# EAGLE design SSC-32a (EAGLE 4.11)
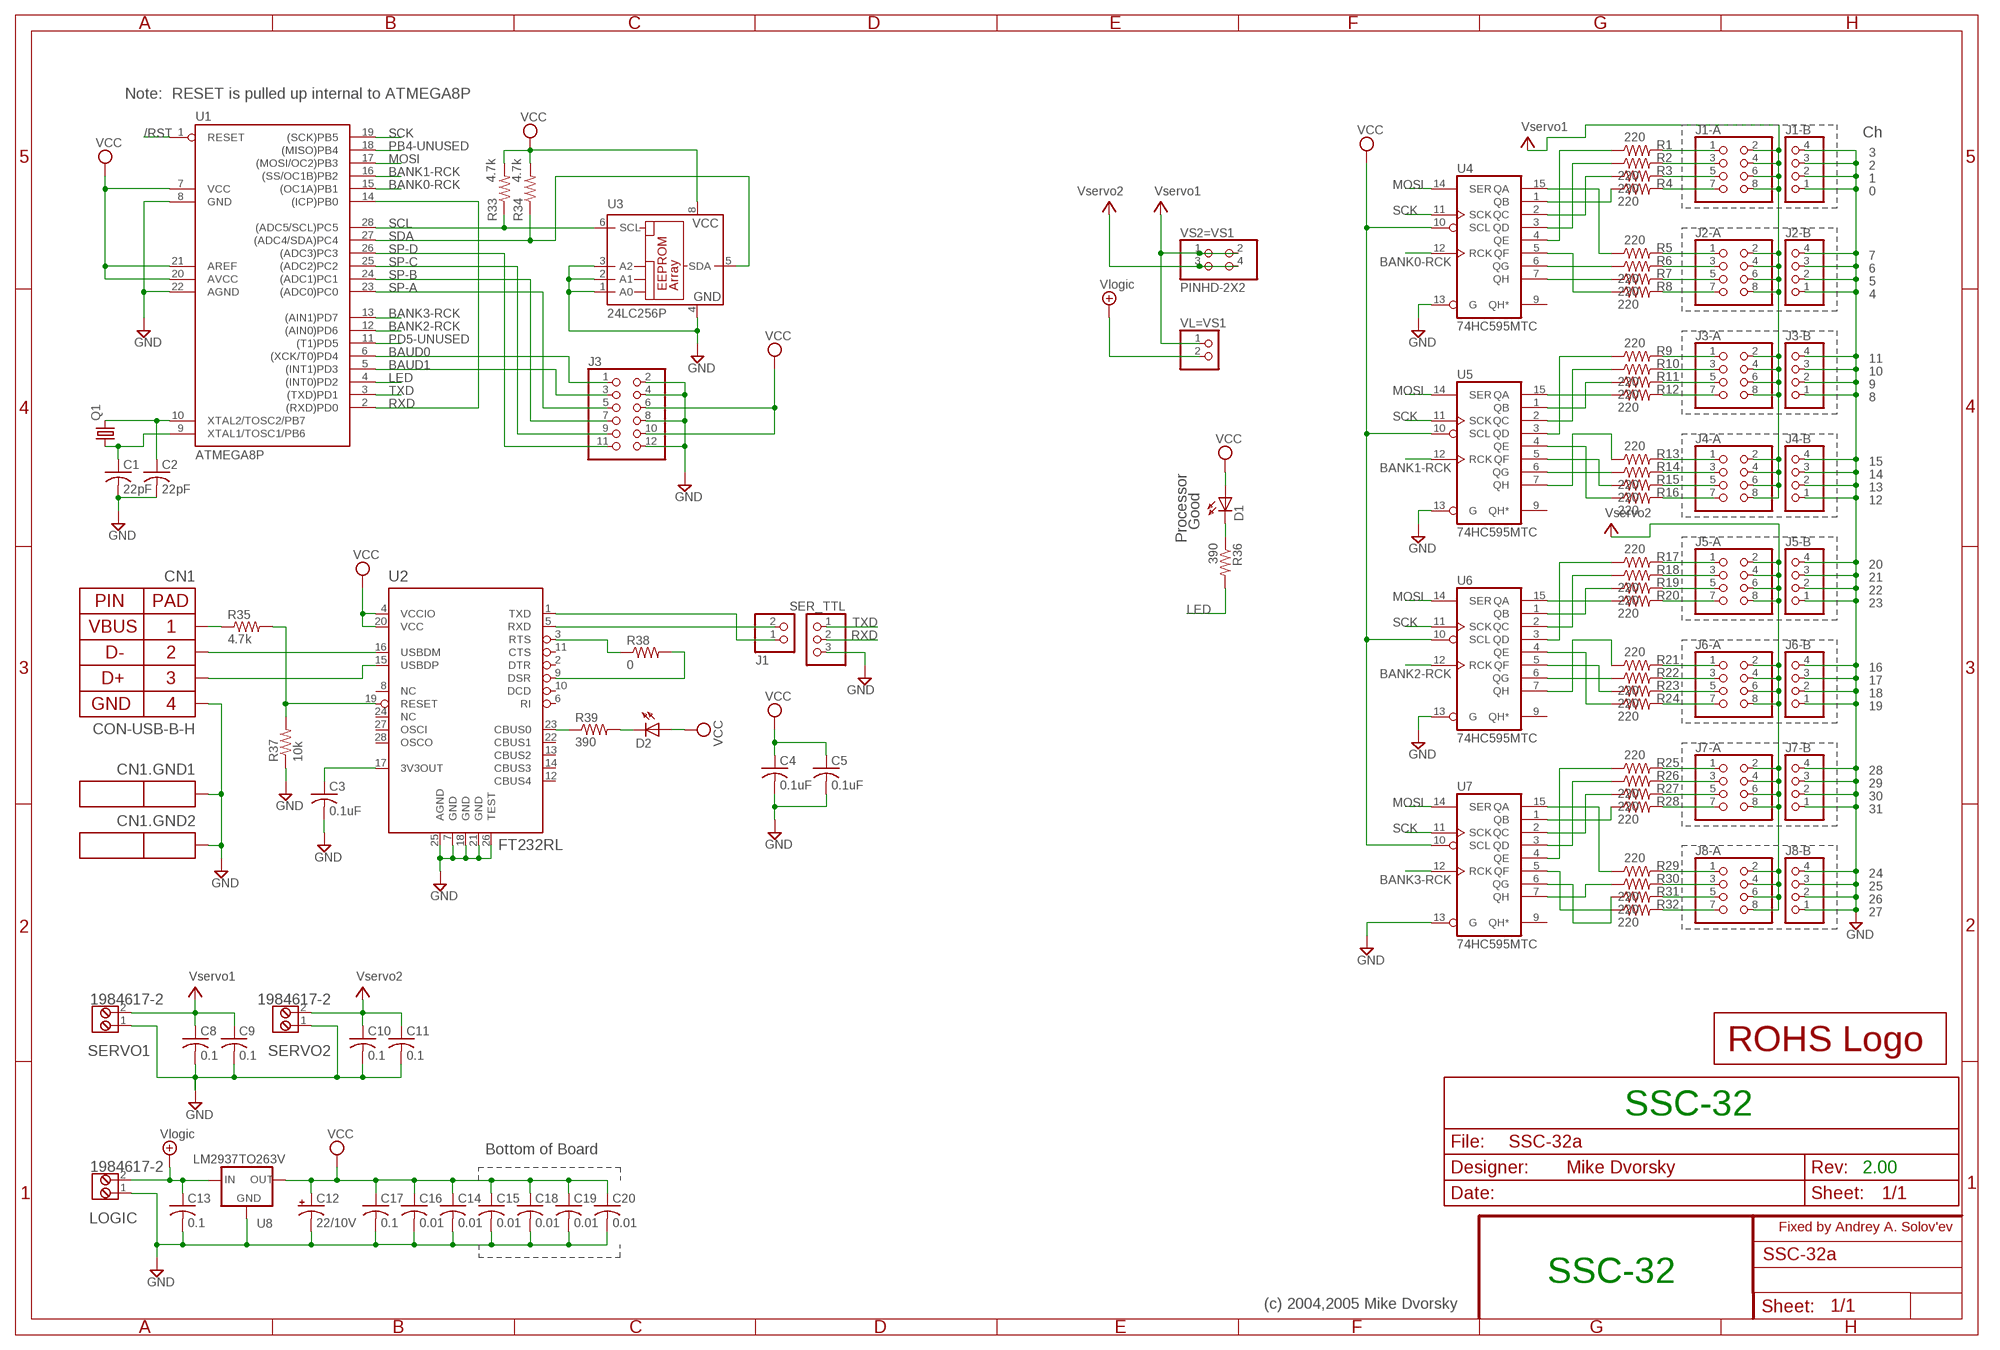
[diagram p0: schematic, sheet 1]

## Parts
C1  22pF  C-USC0603K  [C0603K]
C2  22pF  C-USC0603K  [C0603K]
C3  0.1uF  C-USC0603K  [C0603K]
C4  0.1uF  C-USC0603K  [C0603K]
C5  0.1uF  C-USC0603K  [C0603K]
C8  0.1  C-USC0805K  [C0805K]
C9  0.1  C-USC0805K  [C0805K]
C10  0.1  C-USC0805K  [C0805K]
C11  0.1  C-USC0805K  [C0805K]
C12  22/10V  CPOL-USC/6032-28R  [C/6032-28R]
C13  0.1  C-USC0805K  [C0805K]
C14  0.01  C-USC0603K  [C0603K]
C15  0.01  C-USC0805K  [C0805K]
C16  0.01  C-USC0603K  [C0603K]
C17  0.1  C-USC0805K  [C0805K]
C18  0.01  C-USC0805K  [C0805K]
C19  0.01  C-USC0805K  [C0805K]
C20  0.01  C-USC0805K  [C0805K]
CN1  CON-USB-B-H  [USB-B-H]
D1  LED  [LED-1206]
D2  LED  [LED-1206]
J1  PINHD-1X2SM  [1X02SMALL]
J1-A  PINHD-2X4  [2X04]
J1-B  PINHD-1X4SM"  [1X04SMALL]
J2-A  PINHD-2X4  [2X04]
J2-B  PINHD-1X4SM"  [1X04SMALL]
J3  PINHD-2X6  [2X06]
J3-A  PINHD-2X4  [2X04]
J3-B  PINHD-1X4SM"  [1X04SMALL]
J4-A  PINHD-2X4  [2X04]
J4-B  PINHD-1X4SM"  [1X04SMALL]
J5-A  PINHD-2X4  [2X04]
J5-B  PINHD-1X4SM"  [1X04SMALL]
J6-A  PINHD-2X4  [2X04]
J6-B  PINHD-1X4SM"  [1X04SMALL]
J7-A  PINHD-2X4  [2X04]
J7-B  PINHD-1X4SM"  [1X04SMALL]
J8-A  PINHD-2X4  [2X04]
J8-B  PINHD-1X4SM"  [1X04SMALL]
LOGIC  1984617-2  SCREW_CLAMP2-1984617-2  [1984617-2]
LOGO1  ROHS_LOGO-2_150MIL_TOP  [ROHS_LOGO2_150MIL_TOP]
Q1  CRYTALHC49U-V  [HC49U-V]
R1  220  R-US_R0603  [R0603]
R2  220  R-US_R0603  [R0603]
R3  220  R-US_R0603  [R0603]
R4  220  R-US_R0603  [R0603]
R5  220  R-US_R0603  [R0603]
R6  220  R-US_R0603  [R0603]
R7  220  R-US_R0603  [R0603]
R8  220  R-US_R0603  [R0603]
R9  220  R-US_R0603  [R0603]
R10  220  R-US_R0603  [R0603]
R11  220  R-US_R0603  [R0603]
R12  220  R-US_R0603  [R0603]
R13  220  R-US_R0603  [R0603]
R14  220  R-US_R0603  [R0603]
R15  220  R-US_R0603  [R0603]
R16  220  R-US_R0603  [R0603]
R17  220  R-US_R0603  [R0603]
R18  220  R-US_R0603  [R0603]
R19  220  R-US_R0603  [R0603]
R20  220  R-US_R0603  [R0603]
R21  220  R-US_R0603  [R0603]
R22  220  R-US_R0603  [R0603]
R23  220  R-US_R0603  [R0603]
R24  220  R-US_R0603  [R0603]
R25  220  R-US_R0603  [R0603]
R26  220  R-US_R0603  [R0603]
R27  220  R-US_R0603  [R0603]
R28  220  R-US_R0603  [R0603]
R29  220  R-US_R0603  [R0603]
R30  220  R-US_R0603  [R0603]
R31  220  R-US_R0603  [R0603]
R32  220  R-US_R0603  [R0603]
R33  4.7k  R-US_R0603  [R0603]
R34  4.7k  R-US_R0603  [R0603]
R35  4.7k  R-US_R0603  [R0603]
R36  390  R-US_R0603  [R0603]
R37  10k  R-US_R0603  [R0603]
R38  0  R-US_R0603  [R0603]
R39  390  R-US_R0603  [R0603]
SER_TTL  PINHD-1X3SM  [1X03SMALL]
SERVO1  1984617-2  SCREW_CLAMP2-1984617-2  [1984617-2]
SERVO2  1984617-2  SCREW_CLAMP2-1984617-2  [1984617-2]
U1  ATMEGA8P  [DIL28-3]
U2  FT232RL  [SSOP28DB]
U3  24LC256P  24-LC32P  [DIL8]
U4  74HC595MTC  74595MTC  [TSSOP16]
U5  74HC595MTC  74595MTC  [TSSOP16]
U6  74HC595MTC  74595MTC  [TSSOP16]
U7  74HC595MTC  74595MTC  [TSSOP16]
U8  LM2937TO263V  [TO263V]
VL=VS1  PINHD-1X2SM  [1X02SMALL]
VS2=VS1  PINHD-2X2  [2X02]

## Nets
/RST: U1.1(RESET)
BANK0-RCK: U1.15((OC1A)PB1) U4.12(RCK)
BANK1-RCK: U1.16((SS/OC1B)PB2) U5.12(RCK)
BANK2-RCK: U1.12((AIN0)PD6) U6.12(RCK)
BANK3-RCK: U1.13((AIN1)PD7) U7.12(RCK)
BAUD0: J3.1 U1.6((XCK/T0)PD4)
BAUD1: J3.3 U1.5((INT1)PD3)
GND: C1.2 C2.2 C3.2 C4.2 C5.2 C8.2 C9.2 C10.2 C11.2 C12.- C13.2 C14.2 C15.2 C16.2 C17.2 C18.2 C19.2 C20.2 CN1.GND CN1.GND@1 CN1.GND@2 J1-B.1 J1-B.2 J1-B.3 J1-B.4 J2-B.1 J2-B.2 J2-B.3 J2-B.4 J3-B.1 J3-B.2 J3-B.3 J3-B.4 J3.2 J3.4 J3.8 J3.12 J4-B.1 J4-B.2 J4-B.3 J4-B.4 J5-B.1 J5-B.2 J5-B.3 J5-B.4 J6-B.1 J6-B.2 J6-B.3 J6-B.4 J7-B.1 J7-B.2 J7-B.3 J7-B.4 J8-B.1 J8-B.2 J8-B.3 J8-B.4 LOGIC.1 R37.1 SER_TTL.3 SERVO1.1 SERVO2.1 U1.8(GND) U1.22(AGND) U2.7(GND) U2.18(GND) U2.21(GND) U2.25(AGND) U2.26(TEST) U3.1(A0) U3.2(A1) U3.3(A2) U3.4(GND) U4.13(G) U5.13(G) U6.13(G) U7.13(G) U8.2(GND)
LED: R36.2 U1.4((INT0)PD2)
MOSI: U1.17((MOSI/OC2)PB3) U4.14(SER) U5.14(SER) U6.14(SER) U7.14(SER)
N$1: J1-A.1 R1.2
N$2: J1-A.3 R2.2
N$3: J1-A.5 R3.2
N$4: J1-A.7 R4.2
N$5: J2-A.1 R5.2
N$6: J2-A.3 R6.2
N$7: CN1.VBUS R35.1
N$8: J2-A.5 R7.2
N$9: J2-A.7 R8.2
N$10: J3-A.1 R9.2
N$11: J3-A.3 R10.2
N$12: J3-A.5 R11.2
N$13: J3-A.7 R12.2
N$14: J4-A.1 R13.2
N$15: J4-A.3 R14.2
N$16: J4-A.5 R15.2
N$17: J4-A.7 R16.2
N$18: J5-A.1 R17.2
N$19: J5-A.3 R18.2
N$21: J5-A.5 R19.2
N$25: J5-A.7 R20.2
N$26: J6-A.1 R21.2
N$27: J6-A.3 R22.2
N$28: J6-A.5 R23.2
N$29: J6-A.7 R24.2
N$30: J7-A.1 R25.2
N$31: J7-A.3 R26.2
N$32: J7-A.5 R27.2
N$33: J7-A.7 R28.2
N$34: J8-A.1 R29.2
N$35: J8-A.3 R30.2
N$36: J8-A.5 R31.2
N$37: J8-A.7 R32.2
N$38: R5.1 U4.15(QA)
N$39: R6.1 U4.6(QG)
N$40: R7.1 U4.7(QH)
N$41: R8.1 U4.5(QF)
N$42: R1.1 U4.4(QE)
N$43: R2.1 U4.3(QD)
N$44: R3.1 U4.2(QC)
N$45: R4.1 U4.1(QB)
N$46: R12.1 U5.15(QA)
N$47: R9.1 U5.3(QD)
N$48: R17.1 U6.3(QD)
N$49: R24.1 U6.4(QE)
N$50: R16.1 U5.4(QE)
N$51: R15.1 U5.5(QF)
N$52: R10.1 U5.2(QC)
N$53: R11.1 U5.1(QB)
N$54: R14.1 U5.6(QG)
N$55: R13.1 U5.7(QH)
N$56: C2.1 Q1.2 U1.10(XTAL2/TOSC2/PB7)
N$57: C1.1 Q1.1 U1.9(XTAL1/TOSC1/PB6)
N$58: R18.1 U6.2(QC)
N$59: R19.1 U6.1(QB)
N$60: R20.1 U6.15(QA)
N$61: R23.1 U6.5(QF)
N$62: R22.1 U6.6(QG)
N$63: R21.1 U6.7(QH)
N$64: R28.1 U7.1(QB)
N$65: R27.1 U7.2(QC)
N$66: R35.2 R37.2 U2.19(RESET)
N$67: CN1.D- U2.16(USBDM)
N$68: CN1.D+ U2.15(USBDP)
N$69: D1.C R36.1
N$70: C3.1 U2.17(3V3OUT)
N$72: R26.1 U7.3(QD)
N$73: R25.1 U7.4(QE)
N$76: R29.1 U7.15(QA)
N$77: R30.1 U7.7(QH)
N$78: R32.1 U7.5(QF)
N$79: R38.1 U2.3(RTS)
N$80: R31.1 U7.6(QG)
N$81: R39.1 U2.23(CBUS0)
N$82: D2.C R39.2
N$83: R38.2 U2.9(DSR)
N$84: J1.1 U2.1(TXD)
N$85: J1.2 U2.5(RXD)
PB4-UNUSED: U1.18((MISO)PB4)
PD5-UNUSED: U1.11((T1)PD5)
RXD: SER_TTL.2 U1.2((RXD)PD0) U1.14((ICP)PB0)
SCK: U1.19((SCK)PB5) U4.11(SCK) U5.11(SCK) U6.11(SCK) U7.11(SCK)
SCL: R33.1 U1.28((ADC5/SCL)PC5) U3.6(SCL)
SDA: R34.1 U1.27((ADC4/SDA)PC4) U3.5(SDA)
SP-A: J3.5 U1.23((ADC0)PC0)
SP-B: J3.7 U1.24((ADC1)PC1)
SP-C: J3.9 U1.25((ADC2)PC2)
SP-D: J3.11 U1.26((ADC3)PC3)
TXD: SER_TTL.1 U1.3((TXD)PD1)
VCC: C4.1 C5.1 C12.+ C14.1 C15.1 C16.1 C17.1 C18.1 C19.1 C20.1 D1.A D2.A J3.6 J3.10 R33.2 R34.2 U1.7(VCC) U1.20(AVCC) U1.21(AREF) U2.4(VCCIO) U2.20(VCC) U3.8(VCC) U4.10(SCL) U5.10(SCL) U6.10(SCL) U7.10(SCL) U8.3(OUT)
VLOGIC: C13.1 LOGIC.2 U8.1(IN) VL=VS1.2 ; supply symbol labelled Vlogic
VSERVO1: C8.1 C9.1 J1-A.2 J1-A.4 J1-A.6 J1-A.8 J2-A.2 J2-A.4 J2-A.6 J2-A.8 J3-A.2 J3-A.4 J3-A.6 J3-A.8 J4-A.2 J4-A.4 J4-A.6 J4-A.8 SERVO1.2 VL=VS1.1 VS2=VS1.1 VS2=VS1.2 ; supply symbol labelled Vservo1
VSERVO2: C10.1 C11.1 J5-A.2 J5-A.4 J5-A.6 J5-A.8 J6-A.2 J6-A.4 J6-A.6 J6-A.8 J7-A.2 J7-A.4 J7-A.6 J7-A.8 J8-A.2 J8-A.4 J8-A.6 J8-A.8 SERVO2.2 VS2=VS1.3 VS2=VS1.4 ; supply symbol labelled Vservo2
Unconnected: U2.2(DTR) U2.6(RI) U2.8(NC) U2.10(DCD) U2.11(CTS) U2.12(CBUS4) U2.13(CBUS2) U2.14(CBUS3) U2.22(CBUS1) U2.24(NC) U2.27(OSCI) U2.28(OSCO) U4.9(QH*) U5.9(QH*) U6.9(QH*) U7.9(QH*)

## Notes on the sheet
- Note:  RESET is pulled up internal to ATMEGA8P
- Ch
- 3
- 2
- 1
- 0
- 7
- 6
- 5
- 4
- 11
- 10
- 9
- 8
- 15
- 14
- 13
- 12
- Good
- Processor
- 20
- 21
- 22
- 23
- 16
- 17
- 18
- 19
- 28
- 29
- 30
- 31
- 24
- 25
- 26
- 27
- SSC-32
- Bottom of Board
- 2.00
- Fixed by Andrey A. Solov'ev
- SSC-32
- (c) 2004,2005 Mike Dvorsky

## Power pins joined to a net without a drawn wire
GND: U4.8(GND) U5.8(GND) U6.8(GND) U7.8(GND)
VCC: U4.16(VCC) U5.16(VCC) U6.16(VCC) U7.16(VCC)

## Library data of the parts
C1-C5 C8-C11 C13-C20 = rcl:C-US: CAPACITOR, American symbol
C12 = rcl:CPOL-US: POLARIZED CAPACITOR, American symbol
CN1 = ASUSLabs_0:CON-USB: CON USB
D1 D2 = madlib:LED: LED
J1 VL=VS1 = madlib:PINHD-1X2: 2-position pin header, 0.1" centers
J1-A J2-A J3-A J4-A J5-A J6-A J7-A J8-A = madlib:PINHD-2X4
J1-B J2-B J3-B J4-B J5-B J6-B J7-B J8-B = madlib:PINHD-1X4SM
J3 = madlib:PINHD-2X6
LOGIC SERVO1 SERVO2 = ASUSLabs_0:SCREW_CLAMP2
LOGO1 = ASUSLabs_0:ROHS_LOGO
Q1 = crystal:CRYTAL: CRYSTAL
R1-R39 = rcl:R-US_: RESISTOR, American symbol
SER_TTL = madlib:PINHD-1X3: 1x3 pin header
U1 = madlib:ATMEGA8P: 28 pin DIP package, ATMEGA8
U2 = ASUSLabs_0:FT232RL
U3 = microchip:24-*: Serial EEPROM 32 K/64 K, 1.8 V, I2C
U4-U7 = 74xx-us:74*595: 8-bit SHIFT REGISTER, output latch
U8 = madlib:LM2937
VS2=VS1 = madlib:PINHD-2X2

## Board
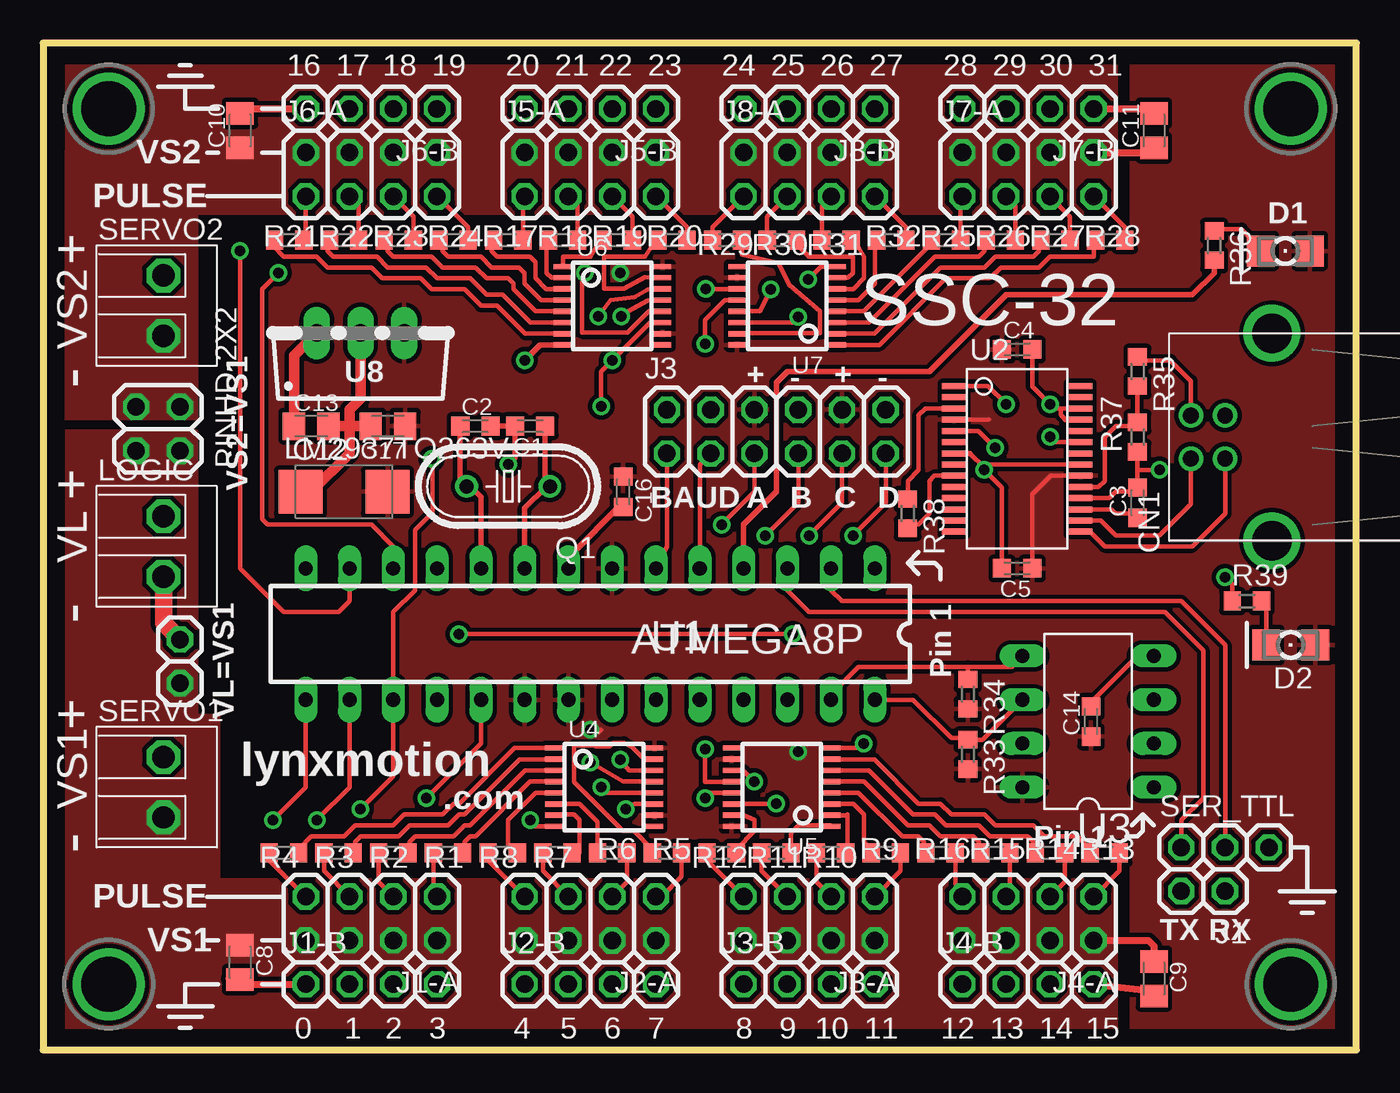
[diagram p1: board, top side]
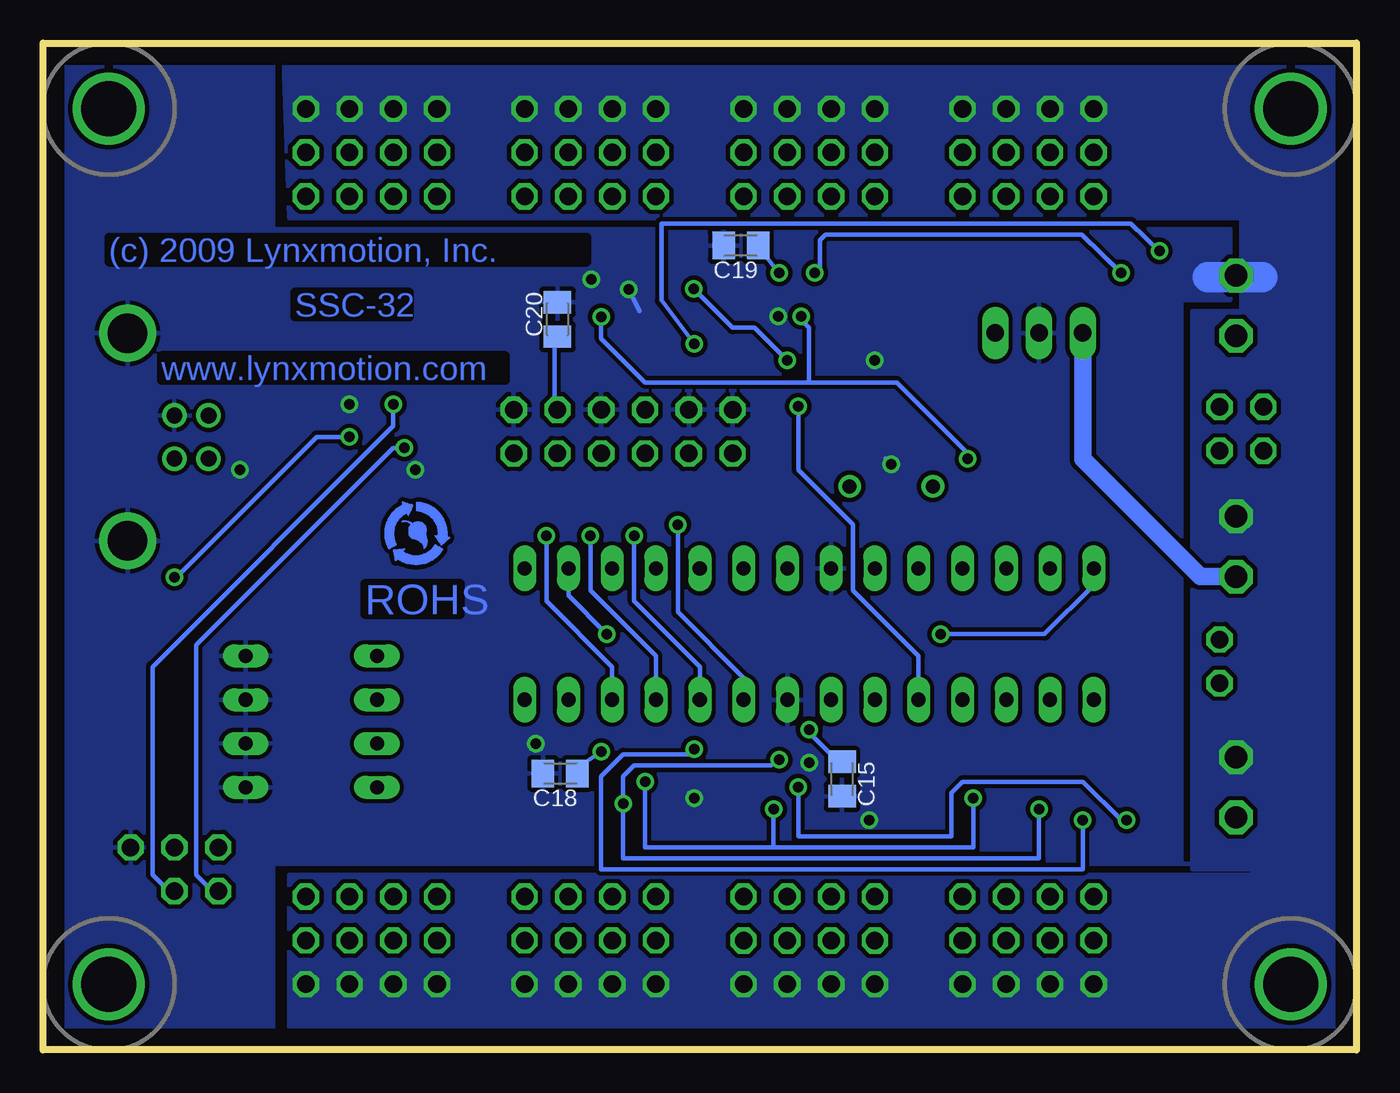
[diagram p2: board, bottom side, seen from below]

Size 76.2 x 58.42 mm. Coordinates in mm from the lower left corner, seen from the top.
Outline: 0,0 76.2,0 76.2,58.42 0,58.42 0,0
Copper layers (1*16): Top 0.035mm / dielectric 1.5mm / Bottom 0.035mm
Design rules "10mils": minimum track width 10mil, minimum drill 24mil, track to track 10mil, track to pad 10mil, pad to pad 10mil, via to via 10mil, smd to smd 10mil, copper to edge 40mil, drill to drill 10mil, minimum pad ring 10mil, minimum via ring 8mil, stop-mask expansion 0mil, vias tented up to drill 0mil, thermal gap 10mil
vRestrict: area 0,0 to 76.2,6.3; area 0,51.4 to 7,58.4; area 69.8,51.4 to 76.2,57.8; area 37.5,45.1 to 44.5,54; area 61,45.7 to 67.9,54.6

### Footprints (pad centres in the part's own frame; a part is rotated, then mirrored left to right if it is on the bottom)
C0603K = smd 1.05 x 1.08: 1 -0.875,0; 2 0.875,0
C0805K = smd 1.3 x 1.6: 1 -1,0; 2 1,0
C/6032-28R = smd 2.55 x 2.5: + 2.525,0; - -2.525,0
USB-B-H = drill 0.914 round: D+ 0,1.25; D- 1.981,1.25; GND 0,-1.25; VBUS 1.981,-1.25 | drill 2.286 round: GND@1 -2.718,-6.02; GND@2 -2.718,6.02
LED-1206 = smd 1.6 x 1.803: A -1.422,0; C 1.422,0
1X02SMALL = drill 1.016 octagon: 1 -1.27,0; 2 1.27,0
2X04 = drill 1.016 octagon: 1 -3.81,-1.27; 2 -3.81,1.27; 3 -1.27,-1.27; 4 -1.27,1.27; 5 1.27,-1.27; 6 1.27,1.27; 7 3.81,-1.27; 8 3.81,1.27
1X04SMALL = drill 1.016 octagon: 1 -3.81,0; 2 -1.27,0; 3 1.27,0; 4 3.81,0
2X06 = drill 1.016 octagon: 1 -6.35,-1.27; 2 -6.35,1.27; 3 -3.81,-1.27; 4 -3.81,1.27; 5 -1.27,-1.27; 6 -1.27,1.27; 7 1.27,-1.27; 8 1.27,1.27; 9 3.81,-1.27; 10 3.81,1.27; 11 6.35,-1.27; 12 6.35,1.27
1984617-2 = drill 1.3 octagon: 1 -1.75,0; 2 1.75,0
HC49U-V = drill 0.813 round: 1 -2.413,0; 2 2.413,0
R0603 = smd 1 x 1.1: 1 -0.85,0; 2 0.85,0
1X03SMALL = drill 1.016 octagon: 1 -2.54,0; 2 0,0; 3 2.54,0
DIL28-3 = drill 0.813 long: 1 -15.24,-3.81; 2 -12.7,-3.81; 3 -10.16,-3.81; 4 -7.62,-3.81; 5 -5.08,-3.81; 6 -2.54,-3.81; 7 0,-3.81; 8 2.54,-3.81; 9 5.08,-3.81; 10 7.62,-3.81; 11 10.16,-3.81; 12 12.7,-3.81; 13 15.24,-3.81; 14 17.78,-3.81; 15 17.78,3.81; 16 15.24,3.81; 17 12.7,3.81; 18 10.16,3.81; 19 7.62,3.81; 20 5.08,3.81; 21 2.54,3.81; 22 0,3.81; 23 -2.54,3.81; 24 -5.08,3.81; 25 -7.62,3.81; 26 -10.16,3.81; 27 -12.7,3.81; 28 -15.24,3.81
SSOP28DB = smd 0.348 x 1.397: 1 -4.225,-3.656; 2 -3.575,-3.656; 3 -2.925,-3.656; 4 -2.275,-3.656; 5 -1.625,-3.656; 6 -0.975,-3.656; 7 -0.325,-3.656; 8 0.325,-3.656; 9 0.975,-3.656; 10 1.625,-3.656; 11 2.275,-3.656; 12 2.925,-3.656; 13 3.575,-3.656; 14 4.225,-3.656; 15 4.225,3.656; 16 3.575,3.656; 17 2.925,3.656; 18 2.275,3.656; 19 1.625,3.656; 20 0.975,3.656; 21 0.325,3.656; 22 -0.325,3.656; 23 -0.975,3.656; 24 -1.625,3.656; 25 -2.275,3.656; 26 -2.925,3.656; 27 -3.575,3.656; 28 -4.225,3.656
DIL8 = drill 0.813 long: 1 -3.81,-3.81; 2 -1.27,-3.81; 3 1.27,-3.81; 4 3.81,-3.81; 5 3.81,3.81; 6 1.27,3.81; 7 -1.27,3.81; 8 -3.81,3.81
TSSOP16 = smd 0.305 x 0.991: 1 -2.275,-2.918; 2 -1.625,-2.918; 3 -0.975,-2.918; 4 -0.325,-2.918; 5 0.325,-2.918; 6 0.975,-2.918; 7 1.625,-2.918; 8 2.275,-2.918; 9 2.275,2.918; 10 1.625,2.918; 11 0.975,2.918; 12 0.325,2.918; 13 -0.325,2.918; 14 -0.975,2.918; 15 -1.625,2.918; 16 -2.275,2.918
TO263V = drill 1.016 long: 1 -2.54,0; 2 0,0; 3 2.54,0
2X02 = drill 1.016 octagon: 1 -1.27,-1.27; 2 -1.27,1.27; 3 1.27,-1.27; 4 1.27,1.27

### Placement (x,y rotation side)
C1  28.26,36.2 180 top
C2  25.08,36.2 0 top
C3  63.5,31.75 90 top
C4  56.52,40.64 0 top
C5  56.52,27.94 180 top
C8  11.43,5.08 270 top
C9  64.45,4.13 270 top
C10  11.43,53.34 90 top
C11  64.45,53.34 90 top
C12  17.46,32.38 0 top
C13  15.56,36.2 0 top
C14  60.8,19.05 90 top
C15  29.84,15.72 270 bottom
C16  33.66,32.38 270 top
C17  20,36.2 180 top
C18  46.2,16.03 180 bottom
C19  35.72,46.67 180 bottom
C20  46.35,42.39 90 bottom
CN1  68.58,35.56 180 top
D1  72.07,46.35 180 top
D2  72.39,23.5 180 top
J1  67.31,9.21 180 top
J1-A  19.05,7.62 180 top
J1-B  19.05,3.81 0 top
J2-A  31.75,7.62 180 top
J2-B  31.75,3.81 0 top
J3  42.55,35.88 0 top
J3-A  44.45,7.62 180 top
J3-B  44.45,3.81 0 top
J4-A  57.15,7.62 180 top
J4-B  57.15,3.81 0 top
J5-A  31.75,50.8 0 top
J5-B  31.75,54.61 180 top
J6-A  19.05,50.8 0 top
J6-B  19.05,54.61 180 top
J7-A  57.15,50.8 0 top
J7-B  57.15,54.61 180 top
J8-A  44.45,50.8 0 top
J8-B  44.45,54.61 180 top
LOGIC  6.99,29.21 270 top
LOGO1  56.52,27.94 0 bottom
Q1  26.99,32.7 180 top
R1  23.5,11.43 180 top
R2  20.32,11.43 180 top
R3  17.14,11.43 180 top
R4  13.97,11.43 180 top
R5  36.2,11.43 0 top
R6  33.02,11.43 0 top
R7  29.84,11.43 180 top
R8  26.67,11.43 180 top
R9  48.9,11.43 0 top
R10  45.72,11.43 180 top
R11  42.55,11.43 180 top
R12  39.37,11.43 180 top
R13  61.59,11.43 0 top
R14  58.42,11.43 0 top
R15  55.24,11.43 0 top
R16  52.07,11.43 0 top
R17  26.99,46.99 0 top
R18  30.16,46.99 0 top
R19  33.34,46.99 0 top
R20  36.51,46.99 0 top
R21  14.29,46.99 0 top
R22  17.46,46.99 0 top
R23  20.64,46.99 0 top
R24  23.81,46.99 0 top
R25  52.39,46.99 0 top
R26  55.56,46.99 0 top
R27  58.74,46.99 0 top
R28  61.91,46.99 0 top
R29  39.69,46.99 180 top
R30  42.86,46.99 180 top
R31  46.04,46.99 180 top
R32  49.21,46.99 0 top
R33  53.66,17.14 270 top
R34  53.66,20.64 270 top
R35  63.5,39.37 270 top
R36  67.94,46.67 270 top
R37  63.5,35.56 90 top
R38  50.16,31.11 270 top
R39  69.85,26.04 0 top
SER_TTL  68.58,11.75 0 top
SERVO1  6.99,15.24 270 top
SERVO2  6.99,43.18 270 top
U1  33.02,24.13 180 top
U2  56.52,34.29 270 top
U3  60.64,19.05 90 top
U4  32.54,15.24 270 top
U5  42.86,15.24 90 top
U6  33.02,43.18 270 top
U7  43.18,43.18 90 top
U8  18.41,41.59 0 top
VL=VS1  7.94,22.54 90 top
VS2=VS1  6.67,36.04 90 top

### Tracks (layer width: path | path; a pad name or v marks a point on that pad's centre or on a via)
BANK0-RCK  (via drill 0.61)
  Top 0.254: U4.12 32.71,14.91 v32.38,15.24 | v13.34,13.34 15.24,15.24 U1.15
  Bottom 0.254: v32.38,15.24 32.38,12.38 23.5,12.38 23.5,14.92 22.86,15.56 15.88,15.56 13.65,13.34 v13.34,13.34
BANK1-RCK  (via drill 0.61)
  Top 0.254: v15.88,13.34 17.78,15.24 U1.16 | v38.42,17.46 38.42,15.56 39.69,15.56 39.7,15.56 U5.12
  Bottom 0.254: v15.88,13.34 15.88,10.48 43.81,10.48 43.81,15.88 42.55,17.14 38.73,17.14 v38.42,17.46
BANK2-RCK  (via drill 0.61)
  Top 0.254: U1.12 20.32,29.21 19.05,30.48 13.02,30.48 12.7,30.8 12.7,44.13 v13.65,45.09 | v31.43,45.09 31.27,45.09 31.27,41.62 33.91,41.62 35.15,42.86 35.88,42.86 35.88,42.85 U6.12
  Bottom 0.254: v13.65,45.09 15.94,47.31 30.8,47.31 31.11,46.99 31.11,45.09 v31.43,45.09
BANK3-RCK  (via drill 0.61)
  Top 0.254: U1.13 17.78,26.04 17.14,25.4 13.97,25.4 11.43,27.94 v11.43,46.35 | v38.42,40.96 38.42,42.35 39.56,43.5 40.32,43.5 40.31,43.51 U7.12
  Bottom 0.254: v11.43,46.35 13.08,47.94 40.32,47.94 40.32,43.5 v38.42,40.96
BAUD0
  Top 0.254: U1.6 36.2,29.21 J3.1
BAUD1
  Top 0.254: U1.5 38.1,33.97 J3.3
GND  (via drill 0.61)
  Top 0.254: U4.8 28.31,12.96 v28.26,13.34 | U5.8 47.36,17.52 v47.62,17.78 | U4.13 33.65,15.56 v31.75,16.67 | U5.13 38.73,14.91 v38.42,14.61 | U7.8 45.14,45.45 v44.39,44.7 | U6.13 35.41,43.51 35.08,43.47 33.98,42.87 v33.56,42.58 | U7.13 41.6,42.85 v42.23,44.13 | C9.2 64.45,3.17 64.14,3.49 63.82,3.49 | C14.2 60.8,20.16 63.5,22.86 U3.4 | U3.4 | U2.18 61.86,32.02 62.23,32.38 63.5,32.38 | 63.5,32.38 C3.2 | 63.5,32.38 63.5,33.66 | 63.5,33.66 R37.1 | 63.5,33.66 v64.77,33.66 | 54.61,33.78 53.78,34.62 | U2.21 54.92,33.97 v54.61,33.66 55.64,32.62 C5.2 | U2.26 59.05,37.22 | 59.05,37.22 58.67,37.22 | C4.2 57.39,38.49 v58.42,37.47 | 59.05,37.22 59.05,36.83 59.32,36.56 | U3.3
  Top 0.305: C16.2 33.66,31.75 30.48,28.57 U1.8 | C2.2 C1.2 27.38,34.37 v26.99,33.97 | 53.78,34.62 U2.7 | v54.61,33.66 54.61,33.78 | 58.67,37.22 v58.42,37.47 | 59.32,36.56 U2.25 | U6.8 28.84,40.91 v27.94,40.01
  Top 0.406: C10.2 11.43,54.29 11.75,54.61 J6-B.4 | C11.2 64.45,54.29 64.14,54.61 J7-B.1 | 10.84,4.08 10.79,4.13 | C8.2 10.84,4.08 | J1-B.1 11.11,3.81 10.84,4.08 | J4-B.4 63.82,3.49
  Top 0.61: 19.05,36.2 C17.2 17.78,36.2 | 17.78,36.2 C13.2 | U8.2 18.41,37.78 17.78,37.15 17.78,36.2 | C12.- 15.56,32.38 17.78,34.61 17.78,36.2
  Bottom 0.254: v47.62,17.78 47.31,17.46 | v38.42,14.61 38.73,14.92 | v44.39,44.7 44.45,44.77 | v42.23,44.13 41.59,42.86
  Bottom 0.305: v26.99,33.97 27.3,34.29
  Bottom 1.778: 5.46,44.83 8.64,44.83
  pour Bottom (no thermals): 0.64,57.47 62.23,57.47 61.91,48.26 0.64,48.26
  pour Bottom (no thermals): 0.64,0.64 61.91,0.64 61.91,10.16 0.64,10.16
  pour Bottom (no thermals): 0.64,53.34 6.67,53.34 6.67,42.86 9.53,42.86 9.53,39.05 9.53,39.37 9.53,15.88 9.53,16.19 9.53,10.48 6.03,10.48 6.03,5.4 0.64,5.4
  pour Bottom: 75.56,57.47 62.87,57.47 62.87,47.62 7.3,47.62 7.3,43.5 10.16,43.5 10.16,10.79 5.08,10.79 62.87,10.79 62.87,0.64 75.56,0.64
LED
  Top 0.305: U1.4 40.64,30.48 42.55,32.38 42.55,38.73 43.18,39.37 51.44,39.37 55.88,43.81 66.67,43.81 67.94,45.09 R36.2
MOSI  (via drill 0.61)
  Top 0.254: v18.41,13.97 20.32,15.88 U1.17 20.32,25.4 21.59,26.67 21.59,30.16 22.61,31.18 22.61,33.72 v22.54,34.29 | U5.14 39.98,14.27 40.01,14.29 v42.55,14.29 | U4.14 33.99,16.21 v33.5,16.83 | U6.14 35.9,44.16 35.88,44.13 35.4,44.13 35.08,44.1 34.32,43.69 32.92,43.5 v32.23,42.58 | U7.14 43.48,42.2 v43.81,42.55
  Bottom 0.254: v18.41,13.97 18.41,11.11 42.55,11.11 v42.55,14.29 42.55,15.88 41.91,16.51 33.97,16.51 v33.5,16.83 | v22.54,34.29 22.54,34.61 26.67,38.73 31.75,38.73 | v43.81,42.55 43.81,41.27 41.27,38.73 31.75,38.73 | 31.75,38.73 31.75,41.91 32.23,42.39 v32.23,42.58
N$1
  Top 0.254: J1-A.1 | R1.2 22.64,9.11 J1-A.1
N$2
  Top 0.254: J1-A.3 | R2.2 19.47,9.74 J1-A.3
N$3
  Top 0.254: J1-A.5 | R3.2 16.3,10.38 J1-A.5
N$4
  Top 0.254: J1-A.7 | R4.2 13.12,11.01 J1-A.7
N$5
  Top 0.254: J2-A.1 35.88,8.89 37.05,10.06 R5.2
N$6
  Top 0.254: J2-A.3 | R6.2 33.87,9.74 J2-A.3
N$7
  Top 0.254: CN1.VBUS 66.6,38.81 65.41,40.01 63.5,40.01 R35.1
N$8
  Top 0.254: J2-A.5 | R7.2 29,10.38 J2-A.5
N$9
  Top 0.254: J2-A.7 | R8.2 25.82,11.01 J2-A.7
N$10
  Top 0.254: J3-A.1 | R9.2 49.74,10.38 J3-A.1
N$11
  Top 0.254: J3-A.3 | R10.2 44.87,9.74 J3-A.3
N$12
  Top 0.254: J3-A.5 | R11.2 41.7,10.38 J3-A.5
N$13
  Top 0.254: J3-A.7 | R12.2 38.52,11.01 J3-A.7
N$14
  Top 0.254: J4-A.1 | R13.2 62.45,10.38 J4-A.1
N$15
  Top 0.254: J4-A.3 | R14.2 59.27,9.74 J4-A.3
N$16
  Top 0.254: J4-A.5 | R15.2 56.09,9.11 J4-A.5
N$17
  Top 0.254: J4-A.7 53.66,8.89 52.92,9.63 R16.2
N$18
  Top 0.254: 28.26,49.53 | 28.26,49.53 J5-A.1 | R17.2 27.84,49.11 28.26,49.53
N$19
  Top 0.254: J5-A.3 | R18.2 31.01,49 J5-A.3
N$20  (via drill 3.17)
  other vias: 3.81,54.61
N$21
  Top 0.254: J5-A.5 | R19.2 34.19,48.36 J5-A.5
N$22  (via drill 3.17)
  other vias: 3.81,3.81
N$23  (via drill 3.17)
  other vias: 72.39,3.81
N$24  (via drill 3.17)
  other vias: 72.39,54.61
N$25
  Top 0.254: J5-A.7 | R20.2 37.36,47.73 J5-A.7
N$26
  Top 0.254: R21.2 15.24,46.99 J6-A.1
N$27
  Top 0.254: R22.2 18.31,49 J6-A.3
N$28
  Top 0.254: R23.2 21.49,48.36 J6-A.5
N$29
  Top 0.254: R24.2 24.66,47.73 J6-A.7
N$30
  Top 0.254: R25.2 53.24,49.43 J7-A.1
N$31
  Top 0.254: R26.2 56.41,49 J7-A.3
N$32
  Top 0.254: R27.2 59.59,48.36 J7-A.5
N$33
  Top 0.254: R28.2 62.76,47.73 J7-A.7
N$34
  Top 0.254: J8-A.1 | R29.2 38.84,47.73 J8-A.1
N$35
  Top 0.254: J8-A.3 | R30.2 42.01,48.36 J8-A.3
N$36
  Top 0.254: J8-A.5 | R31.2 45.19,49 J8-A.5
N$37
  Top 0.254: J8-A.7 | R32.2 50.06,47.73 J8-A.7
N$38
  Top 0.254: U4.15 34.92,16.83 34.25,17.5 33.69,17.82 33.06,17.82 32.86,17.62 32.07,17.62 31.91,17.65 30.8,17.65 30.8,15.56 33.66,12.7 34.29,12.7 35.34,11.64 R5.1
N$39
  Top 0.254: R6.1 32.17,13.23 31.11,14.29 29.84,14.29 29.82,14.27 U4.6
N$40
  Top 0.254: R7.1 31.11,11.43 31.11,13.34 30.8,13.65 29.84,13.65 29.81,13.62 U4.7
N$41
  Top 0.254: U4.5 28.57,14.91 26.99,13.34 26.99,11.75 27.62,11.75 27.3,11.43 R8.1
N$42
  Top 0.254: U4.4 28.27,15.56 25.08,12.38 24.77,12.38 24.45,12.06 24.45,11.43 R1.1
N$43
  Top 0.254: U4.3 27.96,16.21 24.77,13.02 24.45,13.02 23.81,12.38 21.59,12.38 21.27,12.06 21.27,11.43 R2.1
N$44
  Top 0.254: U4.2 27.66,16.86 24.45,13.65 24.13,13.65 23.5,13.02 21.27,13.02 20.64,12.38 18.41,12.38 18.1,12.06 18.1,11.43 R3.1
N$45
  Top 0.254: U4.1 27.36,17.52 24.13,14.29 23.81,14.29 23.18,13.65 20.95,13.65 20.32,13.02 18.1,13.02 17.46,12.38 15.56,12.38 14.82,11.64 R4.1
N$46
  Top 0.254: U5.15 40.68,13.62 41.27,13.34 41.27,12.7 40.22,11.64 R12.1
N$47
  Top 0.254: U5.3 47.01,14.27 47.62,13.65 47.62,12.06 48.05,11.64 R9.1
N$48
  Top 0.254: U6.3 29.19,44.16 28.57,44.77 28.57,45.72 28.26,46.04 26.35,46.04 26.04,46.35 26.04,46.99 R17.1
N$49
  Top 0.254: U6.4 28.89,43.51 27.94,44.45 27.94,45.09 27.62,45.4 26.04,45.4 25.4,46.04 23.5,46.04 23.18,46.35 23.18,46.99 R24.1
N$50
  Top 0.254: U5.4 47.31,14.91 49.85,12.38 50.8,12.38 51.12,12.06 51.12,11.75 51.22,11.64 R16.1
N$51
  Top 0.254: U5.5 47.62,15.56 50.16,13.02 51.44,13.02 52.07,12.38 53.98,12.38 54.29,12.06 54.29,11.43 R15.1
N$52
  Top 0.254: U5.2 46.63,13.62 46.67,13.65 46.67,11.43 R10.1
N$53
  Top 0.254: R11.1 43.4,12.6 43.81,13.02 45.72,13.02 U5.1
N$54
  Top 0.254: U5.6 47.92,16.21 50.48,13.65 51.75,13.65 52.39,13.02 54.29,13.02 54.93,12.38 57.15,12.38 57.47,12.06 57.47,11.43 R14.1
N$55
  Top 0.254: U5.7 48.22,16.86 50.8,14.29 52.07,14.29 52.7,13.65 54.61,13.65 55.24,13.02 57.47,13.02 58.1,12.38 60.01,12.38 60.74,11.64 R13.1
N$56
  Top 0.305: U1.10 25.4,32.07 24.77,32.7 Q1.2 24.45,32.7 24.21,32.94 C2.1
N$57
  Top 0.305: 29.21,32.7 Q1.1 | U1.9 27.94,31.43 29.21,32.7 | C1.1 29.13,32.78 29.21,32.7
N$58
  Top 0.254: U6.2 29.49,44.8 29.21,45.09 29.21,46.99 R18.1
N$59
  Top 0.254: R19.1 32.38,46.99 32.38,46.83 32.07,46.51 31.75,46.04 30.16,46.04 30.16,45.45 U6.1
N$60
  Top 0.254: U6.15 34.92,44.83 33.69,44.17 32.54,44.17 32.54,46.04 34.92,46.04 35.24,46.51 35.56,46.99 R20.1
N$61
  Top 0.254: U6.5 28.58,42.85 27.3,44.13 27.3,44.45 26.99,44.77 25.72,44.77 25.08,45.4 23.18,45.4 22.54,46.04 20.32,46.04 20,46.35 20,46.99 R23.1
N$62
  Top 0.254: U6.6 28.28,42.2 26.67,43.81 25.72,43.81 24.77,44.77 22.86,44.77 22.23,45.4 20,45.4 19.37,46.04 16.83,46.04 16.51,46.35 16.51,46.99 R22.1
N$63
  Top 0.254: U6.7 27.98,41.55 26.35,43.18 25.4,43.18 24.45,44.13 22.54,44.13 21.91,44.77 19.68,44.77 19.05,45.4 16.51,45.4 15.88,46.04 13.97,46.04 13.34,46.67 13.44,46.77 R21.1
N$64
  Top 0.254: U7.1 48.52,40.91 52.39,44.77 54.93,44.77 55.56,45.4 57.78,45.4 58.42,46.04 60.96,46.04 60.96,46.99 R28.1
N$65
  Top 0.254: U7.2 48.22,41.55 52.07,45.4 54.61,45.4 55.24,46.04 57.47,46.04 57.78,46.35 57.78,46.67 57.89,46.77 R27.1
N$66
  Top 0.254: R35.2 R37.2 63.5,36.2 62.23,36.2 61.59,35.56 61.59,33.02 61.24,32.66 U2.19
N$67
  Top 0.254: U2.16 61.36,30.71 62.23,29.84 64.77,29.84 66.6,31.67 CN1.D-
N$68
  Top 0.254: CN1.D+ 68.58,31.11 66.67,29.21 61.59,29.21 60.74,30.07 U2.15
N$69
  Top 0.254: D1.C 70.65,46.51 69.53,47.62 67.94,47.62 R36.1
N$70
  Top 0.254: U2.17 61.98,31.36 62.23,31.11 63.5,31.11
  Top 0.305: 63.5,31.11 C3.1
N$72
  Top 0.254: U7.3 47.92,42.2 51.75,46.04 54.29,46.04 54.61,46.35 54.61,46.99 R26.1
N$73
  Top 0.254: U7.4 47.62,42.85 51.54,46.77 R25.1
N$76
  Top 0.254: R29.1 40.54,46.14 42.67,45.66 43.31,44.39 45.09,42.86 45.09,41.59 40.32,41.59 40.28,41.55 U7.15
N$77
  Top 0.254: U7.7 46.71,44.8 46.99,45.09 46.99,46.04 44.45,46.04 43.5,46.99 R30.1
N$78
  Top 0.254: U7.5 47.31,43.51 48.26,44.45 48.26,46.99 R32.1
N$79
  Top 0.254: U2.3 51.19,37.22 50.8,36.83 50.8,33.66 50.16,33.02 R38.1
N$80
  Top 0.254: U7.6 47.01,44.16 47.62,44.77 47.62,46.04 47.2,46.77 R31.1
N$81  (via drill 0.61)
  Top 0.254: U2.23 58.72,35.27 v58.42,35.56 | R39.1 69,27.01 v68.58,27.43
  Bottom 0.254: v58.42,35.56 60.33,35.56 68.45,27.43 v68.58,27.43
N$82
  Top 0.254: R39.2 70.48,26.04 70.97,25.55 D2.C
N$83
  Top 0.254: U2.9 51.73,33.31 51.44,33.02 51.44,31.11 50.8,30.48 50.16,30.48 R38.2
N$84  (via drill 0.61)
  Top 0.254: U2.1 54.83,38.52 v55.88,37.47
  Bottom 0.254: J1.1 68.9,9.21 69.85,10.16 69.85,22.23 55.88,36.2 v55.88,37.47
N$85  (via drill 0.61)
  Top 0.254: U2.5 54.26,35.91 v55.24,34.92
  Bottom 0.254: J1.2 66.36,9.21 67.31,10.16 67.31,23.5 55.88,34.92 v55.24,34.92
RXD  (via drill 0.61)
  Top 0.254: U1.2 45.72,26.67 46.35,26.04 66.04,26.04 68.58,23.5 SER_TTL.2 | v24.13,24.13 v43.5,24.13
  Bottom 0.254: U1.14 15.24,26.99 18.1,24.13 v24.13,24.13 | v43.5,24.13 45.72,26.35 U1.2
SCK  (via drill 0.61)
  Top 0.254: v22.23,14.61 25.4,17.78 U1.19 | U5.11 39.98,16.21 40.01,16.19 40.64,16.19 v41.27,15.56 | U4.11 34.31,14.27 v33.81,13.97 | v38.44,44.16 U7.11 | v32.38,37.34 32.38,39.37 v33.02,40.01 35.22,42.2 U6.11
  Bottom 0.254: v22.23,14.61 22.23,11.75 33.81,11.75 | 33.81,11.75 41.27,11.75 v41.27,15.56 | 33.81,11.75 v33.81,13.97 | U1.19 25.4,22.86 29.21,26.67 29.21,30.48 32.38,33.66 v32.38,37.34 | v38.44,44.16 36.2,41.91 34.92,41.91 v33.02,40.01
SCL
  Top 0.254: U1.28 50.48,20.32 52.7,18.1 53.66,18.1 R33.1 54.51,18 U3.6 | U3.6
SDA
  Top 0.254: U1.27 45.72,20.64 47.31,22.23 53.66,22.23 | U3.5 | 53.66,22.23 56.2,22.23 U3.5 | 53.66,22.23 R34.1
SP-A  (via drill 0.61)
  Top 0.254: v39.37,30.48 41.27,32.38 J3.5
  Bottom 0.254: U1.23 35.56,21.59 39.37,25.4 v39.37,30.48
SP-B  (via drill 0.61)
  Top 0.254: v41.91,29.84 43.81,31.75 J3.7
  Bottom 0.254: U1.24 38.1,22.23 41.91,26.04 v41.91,29.84
SP-C  (via drill 0.61)
  Top 0.254: v44.45,29.84 46.35,31.75 J3.9
  Bottom 0.254: U1.25 40.64,22.86 44.45,26.67 v44.45,29.84
SP-D  (via drill 0.61)
  Top 0.254: v46.99,29.84 48.9,31.75 J3.11
  Bottom 0.254: U1.26 43.18,22.23 46.99,26.04 v46.99,29.84
TXD
  Top 0.254: U1.3 43.18,26.67 44.45,25.4 65.09,25.4 67.31,23.18 67.31,14.61 66.04,13.34 SER_TTL.1
VCC  (via drill 0.61)
  Top 0.254: v33.5,45.09 33.34,45.24 33.5,45.4 | v43.81,17.3 43.81,17.78 43.97,17.62 | v31.75,18.57 32.38,18.57 32.23,18.41 | U2.20 58.46,33.31 57.4,32.26 57.4,27.94 C5.1 | U2.4 54.37,36.56 54.61,36.58 54.86,36.58
  Bottom 0.254: C19.1 34.72,46.62 v33.5,45.09 | C20.1 45.93,41.39 46.51,41.43 46.51,37.31 J3.10 | C18.1 45.2,16.4 v43.81,17.3 | C15.1 30.05,16.72 31.59,18.26 31.56,18.26 v31.75,18.57
  pour Top: 63.18,57.78 75.56,57.78 75.56,0.64 63.18,0.64 63.18,10.79 11.11,10.79 11.11,20.32 10.16,20.32 10.16,47.62 63.18,47.62
VLOGIC
  Top 0.61: 14.61,36.2 C13.1 14.56,40.27 U8.1
  Top 1.016: VL=VS1.2 6.99,24.77 LOGIC.2
  Bottom 1.016: LOGIC.2 9.04,27.46 15.88,34.29 U8.1
VSERVO1
  Top 0.406: C9.1 64.45,6.03 64.14,6.35 J4-A.2
  pour Top (no thermals): 0.64,0.64 62.23,0.64 62.23,9.84 0.64,9.84
  pour Top (no thermals): 10.16,5.4 10.16,19.37 8.89,19.37 8.89,35.88 0.64,35.88 0.64,5.4
VSERVO2
  Top 0.406: C11.1 64.45,52.39 64.14,52.07 J7-A.8
  pour Top (no thermals): 62.23,48.58 0.64,48.58 0.64,57.47 62.23,57.47
  pour Top (no thermals): 6.67,52.07 6.67,48.42 8.89,48.42 8.89,42.23 8.89,42.55 8.89,36.67 0.48,36.67 0.64,52.07

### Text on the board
Bottom: (c) 2009 Lynxmotion, Inc. | SSC-32 | www.lynxmotion.com | ROHS
tPlace: 16 | 17 | 18 | 19 | 20 | 21 | 22 | 23 | 24 | 25 | 26 | 27 | 28 | 29 | 30 | 31 | VS2 | PULSE | + | SSC-32 | VS2 | + | + | - | - | - | + | BAUD | A | B | C | D | VL | - | Pin 1 | + | lynxmotion | VS1 | .com | Pin 1 | - | PULSE | VS1 | TX | RX | 0 | 1 | 2 | 3 | 4 | 5 | 6 | 7 | 8 | 9 | 10 | 11 | 12 | 13 | 14 | 15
